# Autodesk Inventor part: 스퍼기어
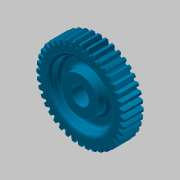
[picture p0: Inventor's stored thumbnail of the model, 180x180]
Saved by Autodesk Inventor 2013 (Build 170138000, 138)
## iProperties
Created: 2018-11
Part Number: 스퍼기어
Material: 알루미늄 6061
Document SubType Name: Modeling
Designer: mduedu
Categories: <?xml version="1.0" encoding="UTF-16"?> <MemberInstance><Categories><FamilyTemplate><FamilyTemplateParameter ValueType="xs:double" Id="1" ObjectReferenceKey="da
Density: 1 g/cm^3
CustomPartVersion: 1
Author: mduedu
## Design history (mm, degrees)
sketch "Sketch1"
  geometry: C1 r 42 at (0, 0)
  constraints: 1 centre point
  dimensions: "d0" = 83.99905 diameter of C1 (= da_da)
extrude "Extrusion1" new body sketch "Sketch1" distance "d1" = 19 (= da_b); taper "d2" = 0 deg
workplane "Work Plane2"
sketch "Sketch2"
  geometry: C1 r 42 at (0, 0) reference; C2 r 40.05 at (0, 0)
  constraints: 1 centre point, 1 coincident
  dimensions: "d3" = 80.10038 diameter of C2 (= da_dw)
feature "피치 지름" sketch "Sketch2" dims "d4" = 10, "d5" = 0
workplane "Work Plane8"
workplane "Work Plane9"
feature "스퍼 기어" dims "da_b" = 19, "da_d" = 80, "da_aw" = 80.10038, "da_da" = 83.99905, "da_df" = 75, "da_dw" = 80.10038, angle "da_beta" = 0 deg, "da_lefttooth" = 0, "da_righttooth" = 0
sketch "스케치3"
  geometry: L1 (-42, 19)-(42, 19) reference; L2 (42, 19)-(42, 0) reference; L3 (42, 0)-(-42, 0) reference; L4 (-42, 0)-(-42, 19) reference; L5 (0, 0)-(0, 19); L6 (42, 0)-(41, 0); L7 (42, 1)-(42, 0); L8 (42, 19)-(41, 19); L9 (42, 18)-(42, 19); L10 (41, 19)-(42, 18); L11 (41, 0)-(42, 1)
  constraints: 14 end point, 2 horizontal, 2 vertical, 1 midpoint
  dimensions: "d49" = 1 distance from line of L8.end L2; "d50" = 1 horizontal distance of L8.end L9.start; "d51" = 1 horizontal distance of L6.end L7.start; "d52" = 1 horizontal distance of L6.end L7.start
revolve "회전1" sketch "스케치3" stored, may be unused: angle "d53" = 90 deg
sketch "스케치4"
  geometry: L1 (-2.5, 8.124)-(2.5, 8.124); L2 (2.5, 8.124)-(2.5, 10.8); L3 (2.5, 10.8)-(-2.5, 10.8); L4 (-2.5, 10.8)-(-2.5, 8.124); A1 r 8.5 centre (0, 0) between (-2.5, 8.124) and (2.5, 8.124); 1 further point
  constraints: 8 end point, 2 parallel, 2 point on circle, 1 centre point, 1 coincident, 1 horizontal, 1 perpendicular
  dimensions: "d54" = 17 diameter of A1; "d56" = 19.3 dimension on A1 L3; "d57" = 5 distance of L2.end L3.end
extrude "돌출2" cut sketch "스케치4" stored distance "d58" = 10; taper "d59" = 0 deg
chamfer "모따기1" distance "d60" = 1; stored, may be unused: second distance "d61" = 2, angle "d62" = 45 deg
sketch "스케치5"
  geometry: C1 r 17.5 at (0, 0); C2 r 28.5 at (0, 0); 1 further point
  constraints: 2 centre point, 2 coincident
  dimensions: "d63" = 35 diameter of C1; "d64" = 57 diameter of C2
extrude "돌출3" cut sketch "스케치5" distance "d65" = 9.5; taper "d66" = 0 deg
fillet "모깎기1" dims "d67" = 3
body "Solid1"
body "Srf1"
node "절단 모서리 투영1"
other parameters: "d16" = 80.10038 (= da_aw), "d17" = 0, "d34" = 4.5 deg (computed from da_z), "d39" = 0, "d41" = 0, "d43" = 80.10038 (= da_aw), "d46" = 80.10038 (= da_aw), "d47" = 0, "d48" = 0
